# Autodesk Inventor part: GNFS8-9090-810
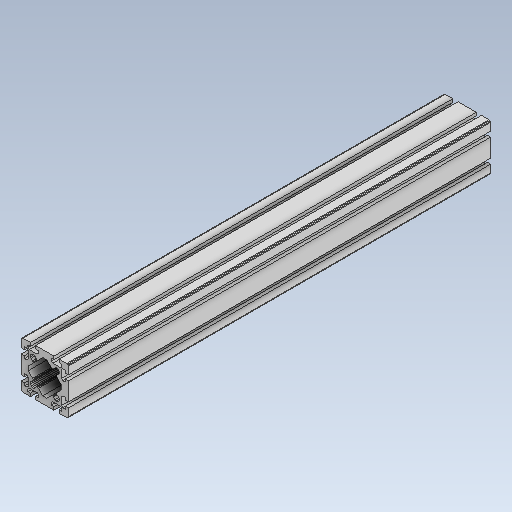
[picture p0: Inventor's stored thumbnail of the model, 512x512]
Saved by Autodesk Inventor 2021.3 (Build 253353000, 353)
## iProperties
Created: 2022-02
Part Number: GNFS8-9090-810
Material: 一般
Document SubType Name: Modeling
Designer: kengo
Density: 1 g/cm^3
Appearance: 既定
Author: kengo
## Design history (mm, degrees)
feature "GNFS8-9090-810"
node "ソリッド1"
